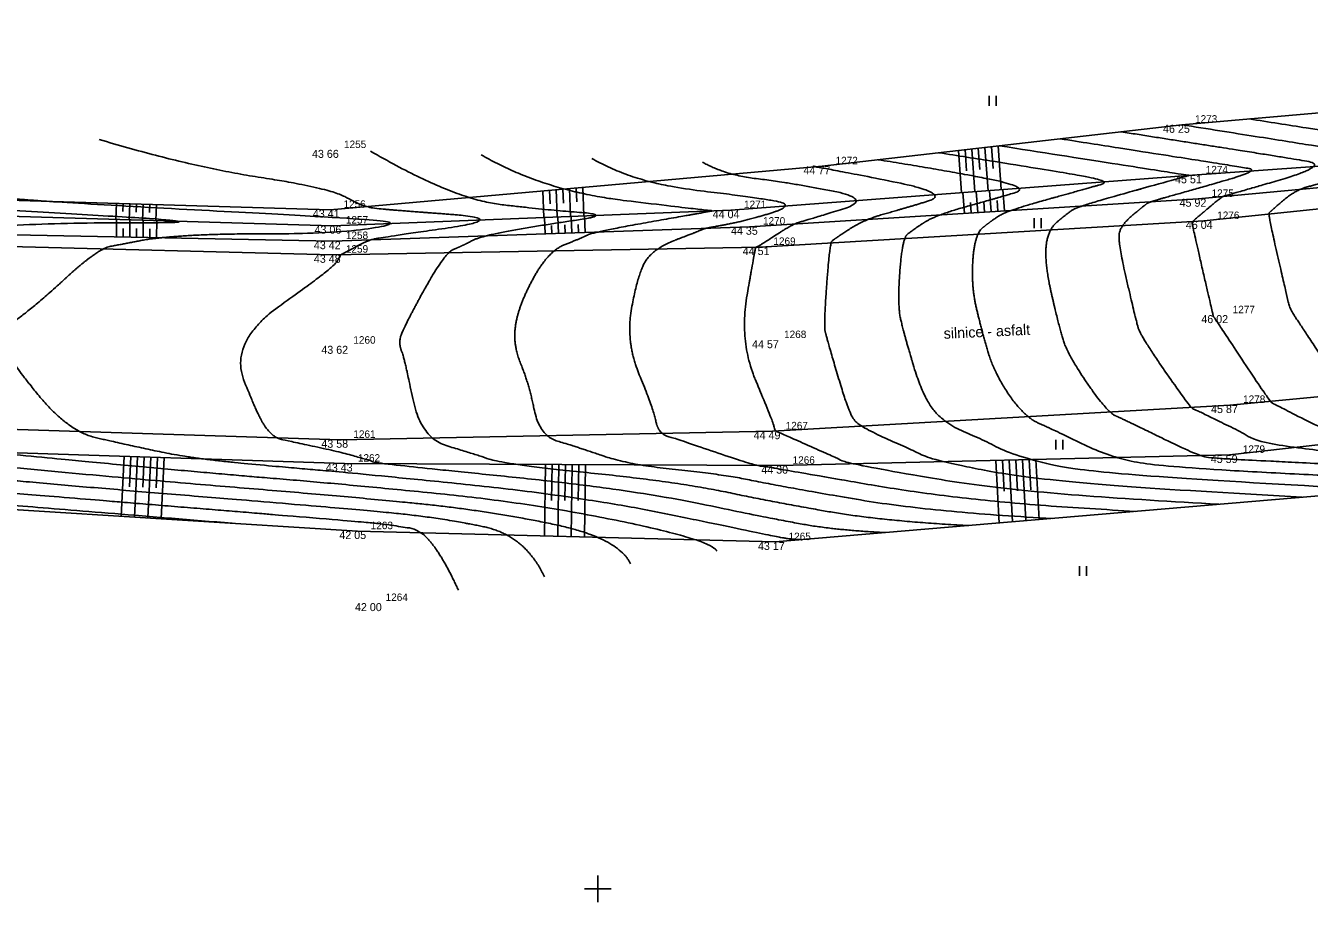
# Model space of a CAD drawing. Extents: x -704017 to -701500, y -1008977 to -1008450.
# Drawn here: x -703121.44 to -703073.34, y -1008850.5 to -1008817.66 of the extents above; entities that cross this region are included whole.
import ezdxf

# ---------------------------------------------------------------- set-up
doc = ezdxf.new("R2010")
doc.units = 0
for name, color, linetype in [('Z_body', 7, 'Continuous'), ('Z_body_cisla', 7, 'Continuous'), ('Z_body_vysky', 7, 'Continuous'), ('Z_hekt_sit', 7, 'Continuous'), ('Z_komunikace', 7, 'Continuous'), ('Z_popis', 7, 'Continuous'), ('Z_teren_hrany_paty', 7, 'Continuous'), ('Z_vrstevnice_hlavni', 7, 'Continuous'), ('Z_vrstevnice_vedlejsi', 7, 'Continuous')]:
    doc.layers.add(name, color=color, linetype=linetype)

# ---------------------------------------------------------------- blocks, each defined once
blk = doc.blocks.new('POINT_DISPLAY')
blk.add_line((0, 0), (0, 0))
blk = doc.blocks.new('Z306')
for p, q in [((-0.13, 0.17), (-0.13, -0.2)), ((0.13, 0.17), (0.13, -0.2))]:
    blk.add_line(p, q)

msp = doc.modelspace()

# ---------------------------------------------------------------- linework, layer by layer
at = {"layer": 'Z_hekt_sit'}
for p, q in [((-703100, -1008849.5), (-703100, -1008850.5)), ((-703100.5, -1008850), (-703099.5, -1008850))]:
    msp.add_line(p, q, dxfattribs=at)
at = {"layer": 'Z_komunikace'}
for p, q in [((-703077.29, -1008824.97), (-703059.3, -1008823.11)), ((-703093.92, -1008825.95), (-703077.29, -1008824.97)), ((-703125.63, -1008825.83), (-703109.94, -1008826.24)), ((-703109.94, -1008826.24), (-703093.92, -1008825.95)), ((-703076.32, -1008831.87), (-703059, -1008830.23)), ((-703093.46, -1008832.85), (-703076.32, -1008831.87)), ((-703126.38, -1008832.64), (-703109.66, -1008833.17)), ((-703109.66, -1008833.17), (-703093.46, -1008832.85))]:
    msp.add_line(p, q, dxfattribs=at)
at = {"layer": 'Z_teren_hrany_paty'}
for p, q in [((-703059.83, -1008819.77), (-703078.12, -1008821.37)), ((-703091.59, -1008822.92), (-703078.12, -1008821.37)), ((-703077.72, -1008823.26), (-703059.56, -1008821.95)), ((-703086.49, -1008822.33), (-703086.37, -1008823.92)), ((-703086.24, -1008822.3), (-703086.18, -1008823.1)), ((-703085.99, -1008822.28), (-703085.87, -1008823.88)), ((-703085.75, -1008822.25), (-703085.69, -1008823.05)), ((-703085.5, -1008822.22), (-703085.37, -1008823.84)), ((-703085.25, -1008822.19), (-703085.19, -1008823.01)), ((-703085, -1008822.16), (-703084.88, -1008823.8)), ((-703077.5, -1008824.14), (-703059.41, -1008822.46)), ((-703110.03, -1008824.55), (-703091.59, -1008822.92)), ((-703095.02, -1008824.57), (-703077.72, -1008823.26)), ((-703102.06, -1008823.85), (-703102.02, -1008824.84)), ((-703101.81, -1008823.82), (-703101.79, -1008824.33)), ((-703101.56, -1008823.8), (-703101.52, -1008824.82)), ((-703101.31, -1008823.78), (-703101.29, -1008824.3)), ((-703101.06, -1008823.76), (-703101.02, -1008824.8)), ((-703100.81, -1008823.74), (-703100.79, -1008824.26)), ((-703100.56, -1008823.71), (-703100.52, -1008824.78)), ((-703086.26, -1008824.69), (-703086.32, -1008823.91)), ((-703085.76, -1008824.66), (-703085.82, -1008823.87)), ((-703085.26, -1008824.62), (-703085.32, -1008823.84)), ((-703084.76, -1008824.59), (-703084.82, -1008823.8)), ((-703125.18, -1008824.11), (-703110.03, -1008824.55)), ((-703118.04, -1008824.32), (-703118.06, -1008824.91)), ((-703117.79, -1008824.32), (-703117.8, -1008824.62)), ((-703117.54, -1008824.33), (-703117.56, -1008824.93)), ((-703117.29, -1008824.34), (-703117.3, -1008824.64)), ((-703117.04, -1008824.35), (-703117.06, -1008824.94)), ((-703116.79, -1008824.35), (-703116.8, -1008824.65)), ((-703116.54, -1008824.36), (-703116.56, -1008824.96)), ((-703094.31, -1008825.19), (-703077.5, -1008824.14)), ((-703086.01, -1008824.67), (-703086.04, -1008824.28)), ((-703085.51, -1008824.64), (-703085.54, -1008824.25)), ((-703085.01, -1008824.61), (-703085.04, -1008824.21)), ((-703125.42, -1008824.7), (-703109.94, -1008825.15)), ((-703118.04, -1008825.57), (-703118.03, -1008824.91)), ((-703117.54, -1008825.58), (-703117.53, -1008824.93)), ((-703117.04, -1008825.59), (-703117.03, -1008824.94)), ((-703116.54, -1008825.6), (-703116.53, -1008824.96)), ((-703109.94, -1008825.15), (-703095.02, -1008824.57)), ((-703101.97, -1008825.45), (-703102, -1008824.84)), ((-703101.47, -1008825.44), (-703101.5, -1008824.82)), ((-703100.97, -1008825.42), (-703101, -1008824.8)), ((-703100.47, -1008825.4), (-703100.5, -1008824.78)), ((-703125.54, -1008825.42), (-703109.94, -1008825.73)), ((-703117.79, -1008825.57), (-703117.79, -1008825.25)), ((-703117.29, -1008825.58), (-703117.29, -1008825.26)), ((-703116.79, -1008825.59), (-703116.79, -1008825.27)), ((-703109.94, -1008825.73), (-703094.31, -1008825.19)), ((-703101.72, -1008825.45), (-703101.73, -1008825.14)), ((-703101.22, -1008825.43), (-703101.23, -1008825.12)), ((-703100.72, -1008825.41), (-703100.73, -1008825.1)), ((-703076.33, -1008833.74), (-703058.79, -1008831.74)), ((-703126.33, -1008833.51), (-703109.49, -1008834.06)), ((-703117.75, -1008833.79), (-703117.86, -1008836.04)), ((-703117.5, -1008833.8), (-703117.55, -1008834.93)), ((-703117.25, -1008833.81), (-703117.36, -1008836.07)), ((-703117, -1008833.81), (-703117.05, -1008834.95)), ((-703116.75, -1008833.82), (-703116.86, -1008836.1)), ((-703116.5, -1008833.83), (-703116.55, -1008834.97)), ((-703116.25, -1008833.84), (-703116.36, -1008836.13)), ((-703109.49, -1008834.06), (-703093.2, -1008834.14)), ((-703101.96, -1008834.1), (-703102, -1008836.77)), ((-703101.71, -1008834.1), (-703101.73, -1008835.44)), ((-703101.46, -1008834.1), (-703101.5, -1008836.79)), ((-703101.21, -1008834.1), (-703101.23, -1008835.45)), ((-703100.96, -1008834.1), (-703101, -1008836.8)), ((-703100.71, -1008834.1), (-703100.73, -1008835.45)), ((-703100.46, -1008834.1), (-703100.5, -1008836.81)), ((-703093.2, -1008834.14), (-703076.33, -1008833.74)), ((-703085.08, -1008833.95), (-703084.96, -1008836.29)), ((-703084.83, -1008833.94), (-703084.77, -1008835.1)), ((-703084.58, -1008833.94), (-703084.46, -1008836.24)), ((-703084.33, -1008833.93), (-703084.27, -1008835.08)), ((-703084.08, -1008833.92), (-703083.96, -1008836.2)), ((-703083.83, -1008833.92), (-703083.77, -1008835.05)), ((-703083.58, -1008833.91), (-703083.46, -1008836.16)), ((-703093.35, -1008837), (-703069.11, -1008834.94)), ((-703126.82, -1008835.48), (-703109.01, -1008836.59)), ((-703109.01, -1008836.59), (-703093.35, -1008837))]:
    msp.add_line(p, q, dxfattribs=at)
at = {"layer": 'Z_vrstevnice_hlavni'}
for points in [[(-703080.395, -1008821.632), (-703077.985, -1008822.009), (-703074.282, -1008822.589), (-703072.547, -1008822.887), (-703076.404, -1008824.006), (-703076.612, -1008824.058), (-703077.36, -1008824.693), (-703077.725, -1008824.996), (-703077.732, -1008825.092), (-703076.942, -1008828.513), (-703076.929, -1008828.557), (-703076.658, -1008828.949), (-703074.829, -1008831.729), (-703074.619, -1008831.857), (-703071.891, -1008833.234), (-703064.736, -1008833.584), (-703060.227, -1008833.919)], [(-703138.257, -1008822.483), (-703136.057, -1008823.22), (-703125.3, -1008824.405), (-703113.512, -1008825.046), (-703120.426, -1008825.032), (-703125.529, -1008825.355), (-703127.368, -1008825.287), (-703130.609, -1008825.34), (-703132.675, -1008825.34), (-703132.792, -1008826.779), (-703135.985, -1008828.39), (-703132.86, -1008830.047), (-703128.993, -1008832.432), (-703127.879, -1008832.643), (-703126.366, -1008832.889), (-703123.879, -1008833.46), (-703123.153, -1008833.614), (-703114.236, -1008834.449), (-703109.34, -1008834.848), (-703102.335, -1008835.556), (-703095.727, -1008836.938), (-703095.544, -1008837.333)], [(-703104.368, -1008822.497), (-703102.03, -1008823.843), (-703095.973, -1008824.569), (-703095.629, -1008824.594), (-703095.983, -1008824.645), (-703100.192, -1008825.393), (-703100.598, -1008825.612), (-703101.852, -1008826.094), (-703102.94, -1008828.07), (-703103.204, -1008829.566), (-703102.584, -1008831.048), (-703102.183, -1008833.022), (-703100.87, -1008833.409), (-703098.817, -1008834.112), (-703095.308, -1008834.467), (-703093.24, -1008834.899), (-703087.513, -1008835.882), (-703082.979, -1008836.119)], [(-703089.497, -1008822.679), (-703087.279, -1008823.026), (-703083.722, -1008823.714), (-703085.014, -1008824.109), (-703087.35, -1008824.755), (-703088.214, -1008825.321), (-703088.594, -1008825.636), (-703088.772, -1008828.132), (-703088.535, -1008829.161), (-703087.877, -1008831.4), (-703087.126, -1008832.488), (-703085.674, -1008833.128), (-703084.046, -1008833.923), (-703080.48, -1008834.535), (-703070.484, -1008835.057)], [(-703181.712, -1008831.043), (-703179.751, -1008831.188), (-703177.57, -1008829.807), (-703176.812, -1008829.937), (-703176.482, -1008829.975), (-703161.792, -1008831.725), (-703148.815, -1008833.138), (-703142.02, -1008833.967), (-703129.638, -1008834.962), (-703126.754, -1008835.215), (-703125.275, -1008835.353), (-703113.697, -1008836.298)]]:
    msp.add_open_spline(points, degree=2, dxfattribs=at)
at = {"layer": 'Z_vrstevnice_vedlejsi'}
for points in [[(-703234.416, -1008819.676), (-703234.819, -1008818.735), (-703233.384, -1008817.353), (-703224.783, -1008818.458), (-703210.015, -1008821.579), (-703209.635, -1008821.658), (-703208.635, -1008821.853), (-703202.405, -1008822.86), (-703194.125, -1008824.237), (-703191.67, -1008824.705), (-703186.62, -1008825.361), (-703181.332, -1008823.654), (-703176.67, -1008825.425), (-703172.213, -1008823.237), (-703168.452, -1008822.643), (-703163.45, -1008824.5), (-703159.99, -1008824.38), (-703159.232, -1008825.904), (-703155.255, -1008826.65), (-703148.393, -1008830.68), (-703142.077, -1008831.746), (-703137.248, -1008832.661), (-703134.789, -1008833.06), (-703126.401, -1008833.794), (-703116.996, -1008834.675), (-703109.253, -1008835.307), (-703104.091, -1008835.828), (-703099.223, -1008836.846), (-703098.771, -1008837.822)], [(-703227.661, -1008821.338), (-703228.544, -1008819.277), (-703228.029, -1008818.781), (-703224.941, -1008819.177), (-703219.64, -1008820.298), (-703209.757, -1008822.368), (-703200.654, -1008824.137), (-703194.808, -1008825.352), (-703180.208, -1008828.229), (-703176.899, -1008828.797), (-703167.598, -1008829.854), (-703163.852, -1008830.077), (-703161.321, -1008830.357), (-703156.573, -1008831.155), (-703142.101, -1008832.921), (-703139.704, -1008833.114), (-703126.518, -1008834.268), (-703119.756, -1008834.901), (-703109.167, -1008835.765), (-703105.848, -1008836.1), (-703102.718, -1008836.755), (-703101.997, -1008838.311)], [(-703075.594, -1008821.149), (-703070.774, -1008821.905), (-703067.267, -1008822.506), (-703069.557, -1008823.17), (-703071.063, -1008823.542), (-703071.843, -1008824.205), (-703072.019, -1008824.425), (-703071.454, -1008826.873), (-703071.231, -1008827.97), (-703070.459, -1008829.111), (-703069.094, -1008831.186), (-703068.078, -1008831.809), (-703066.477, -1008832.617), (-703062.279, -1008832.822), (-703058.882, -1008833.075), (-703055.109, -1008833.404)], [(-703078.12, -1008821.37), (-703072.528, -1008822.247), (-703069.907, -1008822.696), (-703072.981, -1008823.588), (-703073.838, -1008823.8), (-703074.803, -1008824.621), (-703074.884, -1008824.721), (-703074.192, -1008827.72), (-703074.084, -1008828.246), (-703073.715, -1008828.793), (-703071.961, -1008831.457), (-703071.349, -1008831.833), (-703069.184, -1008832.925), (-703063.508, -1008833.203), (-703058.914, -1008833.544), (-703057.691, -1008833.651)], [(-703129.66, -1008821.922), (-703125.183, -1008823.421), (-703123.531, -1008823.914), (-703121.573, -1008824.215), (-703109.989, -1008824.824), (-703107.047, -1008825.038), (-703109.94, -1008825.456), (-703114.185, -1008825.448), (-703116.57, -1008825.598), (-703117.74, -1008825.83), (-703118.742, -1008826.01), (-703121.105, -1008828.192), (-703122.492, -1008829.17), (-703122.169, -1008830), (-703119.878, -1008832.846), (-703117.75, -1008833.335), (-703115.209, -1008833.873), (-703111.477, -1008834.223), (-703109.427, -1008834.39), (-703100.578, -1008835.283), (-703093.339, -1008836.798), (-703092.787, -1008836.892), (-703092.35, -1008836.915)], [(-703118.684, -1008821.921), (-703115.287, -1008822.936), (-703110.023, -1008823.744), (-703108.81, -1008824.442), (-703107.886, -1008824.553), (-703103.241, -1008824.89), (-703108.015, -1008825.58), (-703108.595, -1008825.684), (-703109.581, -1008826.216), (-703109.629, -1008826.234), (-703109.9, -1008826.727), (-703113.822, -1008829.494), (-703112.693, -1008832.402), (-703112.137, -1008833.091), (-703111.621, -1008833.21), (-703109.569, -1008833.645), (-703108.431, -1008833.98), (-703108.179, -1008834.066), (-703098.821, -1008835.011), (-703093.306, -1008836.165), (-703091.029, -1008836.555), (-703089.227, -1008836.65)], [(-703082.671, -1008821.894), (-703077.85, -1008822.647), (-703076.036, -1008822.932), (-703075.186, -1008823.077), (-703077.591, -1008823.775), (-703079.32, -1008824.254), (-703079.48, -1008824.358), (-703080.442, -1008825.156), (-703080.492, -1008825.852), (-703079.84, -1008828.675), (-703079.666, -1008829.268), (-703077.81, -1008831.955), (-703077.61, -1008832.044), (-703076.324, -1008832.671), (-703074.598, -1008833.542), (-703065.965, -1008833.965), (-703062.723, -1008834.206)], [(-703108.516, -1008822.359), (-703105.42, -1008824.143), (-703101.929, -1008824.561), (-703099.435, -1008824.742), (-703101.999, -1008825.113), (-703104.394, -1008825.538), (-703105.089, -1008825.914), (-703105.741, -1008826.164), (-703107.361, -1008829.11), (-703107.451, -1008829.621), (-703107.239, -1008830.128), (-703106.634, -1008833.11), (-703104.651, -1008833.695), (-703103.498, -1008834.089), (-703097.065, -1008834.739), (-703093.273, -1008835.532), (-703089.271, -1008836.219), (-703086.103, -1008836.384)], [(-703087.221, -1008822.417), (-703082.593, -1008823.141), (-703080.78, -1008823.492), (-703081.438, -1008823.693), (-703084.674, -1008824.588), (-703085.302, -1008825), (-703085.877, -1008825.476), (-703086.012, -1008827.372), (-703085.637, -1008828.999), (-703085.14, -1008830.689), (-703084.021, -1008832.31), (-703082.986, -1008832.766), (-703080.776, -1008833.845), (-703078.721, -1008834.198), (-703071.216, -1008834.59), (-703068.422, -1008834.727), (-703067.713, -1008834.779)], [(-703084.946, -1008822.155), (-703077.907, -1008823.255), (-703077.838, -1008823.269), (-703077.863, -1008823.277), (-703081.997, -1008824.421), (-703082.391, -1008824.679), (-703083.159, -1008825.316), (-703083.252, -1008826.612), (-703082.738, -1008828.837), (-703082.403, -1008829.978), (-703080.916, -1008832.133), (-703080.298, -1008832.405), (-703077.507, -1008833.768), (-703076.963, -1008833.861), (-703074.976, -1008833.965), (-703067.193, -1008834.346), (-703065.218, -1008834.493)], [(-703100.219, -1008822.634), (-703098.641, -1008823.543), (-703094.033, -1008824.095), (-703092.549, -1008824.383), (-703094.539, -1008824.99), (-703095.991, -1008825.248), (-703096.107, -1008825.311), (-703097.964, -1008826.023), (-703098.518, -1008827.031), (-703098.957, -1008829.511), (-703097.929, -1008831.967), (-703097.733, -1008832.934), (-703097.089, -1008833.124), (-703094.136, -1008834.135), (-703093.551, -1008834.194), (-703093.207, -1008834.267), (-703085.754, -1008835.545), (-703079.856, -1008835.853)], [(-703096.071, -1008822.772), (-703095.251, -1008823.244), (-703092.859, -1008823.53), (-703089.606, -1008824.16), (-703092.165, -1008824.94), (-703092.704, -1008825.09), (-703093.944, -1008825.903), (-703094.076, -1008825.953), (-703094.097, -1008825.992), (-703094.709, -1008829.455), (-703093.467, -1008832.424), (-703093.351, -1008832.822), (-703093.336, -1008832.843), (-703091.05, -1008833.851), (-703090.584, -1008834.078), (-703083.996, -1008835.208), (-703076.732, -1008835.588)], [(-703091.922, -1008822.909), (-703091.861, -1008822.944), (-703091.684, -1008822.965), (-703086.664, -1008823.937), (-703088.589, -1008824.524), (-703090.027, -1008824.922), (-703091.125, -1008825.642), (-703091.311, -1008825.796), (-703091.533, -1008828.893), (-703091.433, -1008829.323), (-703090.614, -1008832.111), (-703090.231, -1008832.665), (-703088.362, -1008833.489), (-703087.315, -1008834), (-703082.238, -1008834.872), (-703073.608, -1008835.322)], [(-703216.235, -1008824.104), (-703210.008, -1008823.987), (-703204.408, -1008824.831), (-703198.008, -1008825.602), (-703195.032, -1008826.221), (-703193.951, -1008826.434), (-703176.856, -1008829.367), (-703168.28, -1008830.342), (-703161.573, -1008831.141), (-703155.649, -1008831.786), (-703142.06, -1008833.444), (-703134.671, -1008834.038), (-703126.636, -1008834.741), (-703122.515, -1008835.127), (-703109.08, -1008836.223), (-703107.605, -1008836.372), (-703106.214, -1008836.663), (-703105.224, -1008838.801)]]:
    msp.add_open_spline(points, degree=2, dxfattribs=at)

# ---------------------------------------------------------------- block references
at = {"layer": 'Z_body'}
for p in [(-703078.12, -1008821.37), (-703110.01, -1008822.31), (-703091.59, -1008822.92), (-703077.72, -1008823.26), (-703077.5, -1008824.14), (-703110.03, -1008824.55), (-703095.02, -1008824.57), (-703077.29, -1008824.97), (-703109.94, -1008825.15), (-703094.31, -1008825.19), (-703109.94, -1008825.73), (-703093.92, -1008825.95), (-703109.94, -1008826.24), (-703076.71, -1008828.5), (-703109.66, -1008829.65), (-703093.52, -1008829.44), (-703076.32, -1008831.87), (-703109.66, -1008833.17), (-703093.46, -1008832.85), (-703109.49, -1008834.06), (-703093.2, -1008834.14), (-703076.33, -1008833.74), (-703109.01, -1008836.59), (-703093.35, -1008837), (-703108.45, -1008839.29)]:
    msp.add_blockref('POINT_DISPLAY', p, dxfattribs=at)
at = {"layer": 'Z_popis'}
for p in [(-703085.2, -1008820.46), (-703083.52, -1008825.04), (-703082.71, -1008833.34), (-703081.82, -1008838.07)]:
    msp.add_blockref('Z306', p, dxfattribs=at)

# ---------------------------------------------------------------- texts
at = {"layer": 'Z_body_cisla'}
for s, p in [('1273', (-703077.62, -1008821.29)), ('1255', (-703109.51, -1008822.24)), ('1272', (-703091.09, -1008822.85)), ('1274', (-703077.22, -1008823.19)), ('1275', (-703077, -1008824.07)), ('1256', (-703109.53, -1008824.48)), ('1271', (-703094.52, -1008824.49)), ('1257', (-703109.44, -1008825.07)), ('1270', (-703093.81, -1008825.11)), ('1276', (-703076.79, -1008824.9)), ('1258', (-703109.44, -1008825.65)), ('1259', (-703109.44, -1008826.16)), ('1269', (-703093.42, -1008825.87)), ('1277', (-703076.21, -1008828.43)), ('1260', (-703109.16, -1008829.57)), ('1268', (-703093.02, -1008829.36)), ('1278', (-703075.82, -1008831.79)), ('1267', (-703092.96, -1008832.78)), ('1261', (-703109.16, -1008833.1)), ('1279', (-703075.83, -1008833.66)), ('1262', (-703108.99, -1008833.99)), ('1266', (-703092.7, -1008834.07)), ('1263', (-703108.51, -1008836.52)), ('1265', (-703092.85, -1008836.93)), ('1264', (-703107.95, -1008839.21))]:
    msp.add_text(s, height=0.28, dxfattribs=at).set_placement(p)
at = {"layer": 'Z_body_vysky'}
for s, p in [('46 25', (-703078.82, -1008821.67)), ('43 66', (-703110.71, -1008822.61)), ('44 77', (-703092.29, -1008823.22)), ('45 51', (-703078.37, -1008823.56)), ('43 41', (-703110.68, -1008824.85)), ('45 92', (-703078.2, -1008824.44)), ('44 04', (-703095.695, -1008824.87)), ('46 04', (-703077.965, -1008825.27)), ('43 06', (-703110.615, -1008825.45)), ('44 35', (-703095.01, -1008825.49)), ('43 42', (-703110.64, -1008826.03)), ('44 51', (-703094.57, -1008826.25)), ('43 48', (-703110.64, -1008826.54)), ('46 02', (-703077.385, -1008828.8)), ('43 62', (-703110.36, -1008829.95)), ('44 57', (-703094.22, -1008829.74)), ('45 87', (-703077.02, -1008832.17)), ('43 58', (-703110.36, -1008833.47)), ('44 49', (-703094.16, -1008833.15)), ('43 43', (-703110.19, -1008834.36)), ('44 30', (-703093.875, -1008834.44)), ('45 59', (-703077.03, -1008834.04)), ('42 05', (-703109.685, -1008836.89)), ('43 17', (-703094, -1008837.3)), ('42 00', (-703109.1, -1008839.59))]:
    msp.add_text(s, height=0.3, dxfattribs=at).set_placement(p)
at = {"layer": 'Z_popis'}
msp.add_text('silnice - asfalt', height=0.4, rotation=2.7, dxfattribs=at).set_placement((-703087.03, -1008829.39))

doc.saveas('drawing.dxf')
